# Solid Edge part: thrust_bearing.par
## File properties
Title: Thrust bearing
Author: Abhinav Rai
Template: Normal.par
Last saved by: Cadcim
Revision: 11
Application: Solid Edge
Material: aluminum
Accuracy: 0.99
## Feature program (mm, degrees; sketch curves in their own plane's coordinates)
sketch for "unnamed RevolvedProtrusion 1" plane through (0, 0, 0) normal (0, -1, 0) x-axis (1, 0, 0)
  line (47.625, 16.8036) -> (66.929, 16.8036)
  line (66.929, 16.8036) -> (73.025, 10.7076)
  line (73.025, 10.7076) -> (73.025, -12.0254)
  line (73.025, -12.0254) -> (66.929, -18.1214)
  line (66.929, -18.1214) -> (47.625, -18.1214)
  line (47.625, -18.1214) -> (47.625, -7.0089)
  line (61.5714, -7.0089) -> (47.625, -7.0089)
  line (61.5714, 5.6911) -> (61.5714, -7.0089)
  line (47.625, 5.6911) -> (61.5714, 5.6911)
  line (47.625, 5.6911) -> (47.625, 16.8036)
revolve "unnamed RevolvedProtrusion 1" add full turn 360 deg
sketch for "unnamed RevolvedProtrusion 2" plane through (0, 0, 0) normal (1, 0, 0) x-axis (0, 1, 0)
  line (69.977, 13.7556) -> (73.0652, 13.7556)
  line (73.0652, 13.7556) -> (74.6125, 12.2083)
  line (74.6125, 12.2083) -> (74.6125, -13.4669)
  line (74.6125, -13.4669) -> (73.006, -15.0734)
  line (73.006, -15.0734) -> (69.977, -15.0734)
revolve "unnamed RevolvedProtrusion 2" add full turn 360 deg
sketch for "unnamed RevolvedProtrusion 3" plane through (0, 0, 0) normal (0, -1, 0) x-axis (1, 0, 0)
revolve "unnamed RevolvedProtrusion 3" add full turn 360 deg about sketch line (-54.9674, 10.1232) -> (-54.9674, -18.1214)
pattern "unnamed Pattern 1" of "unnamed RevolvedProtrusion 3"
pattern "unnamed Pattern 2"
sketch for "unnamed RevolvedProtrusion 4" plane through (-58.658, 0, 54.4016) normal (0, -1, 0) x-axis (1, 0, 0)
revolve "unnamed RevolvedProtrusion 4" add full turn 360 deg
sketch for "unnamed RevolvedProtrusion 5" plane through (0, -119.6728, -47.0787) normal (1, 0, 0) x-axis (0, 1, 0)
revolve "unnamed RevolvedProtrusion 5" add full turn 360 deg
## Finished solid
Body 1: solid body, 39 faces, 39 edges, 25 vertices.
  Faces by surface: torus 25, plane 6, cone 4, cylinder 4
  Edges by curve: circle 39
Bounding box of the edges (mm; curved faces can reach further): 149.225 x 149.225 x 34.925, from (-74.6125, -74.6125, -18.1214) to (74.6125, 74.6125, 16.8036).
Cylindrical faces by radius (mm): R47.625 x2, R61.5714 x1, R74.6125 x1
Conical faces (half-angle, radius in mm at the cone's reference point): 45 deg R66.929 x1, 45 deg R73.025 x1, 45 deg R73.0652 x1, 45 deg R74.6125 x1
Toroidal faces (ring radius, tube radius in mm): R-1.578 r6.604 x25
Planar faces by outward normal: +z 3, -z 3
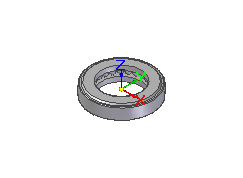
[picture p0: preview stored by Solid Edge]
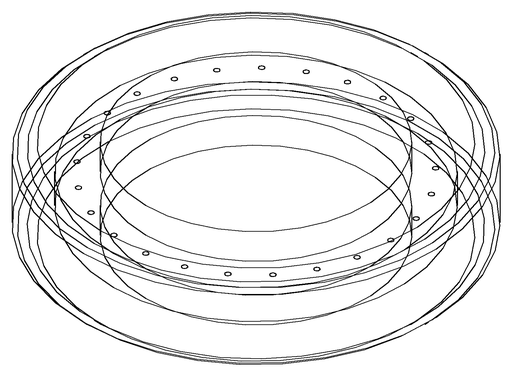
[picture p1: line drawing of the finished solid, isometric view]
